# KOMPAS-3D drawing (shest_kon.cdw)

Referenced files: Чертеж Пример.cdw
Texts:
  Шестерня коническая
  Текст на чертеже
  Размерные надписи
  Шероховатость
  Линия-выноска #1
  Линия-выноска #2
  Линия-выноска #3
  Отклонения формы и база
  Заголовок таблицы
  Ячейка таблицы
  Стрелка вида
  Обозначение изменения
  Фигурная скобка
  Номер узла
  Марка координационной оси
  VRCB
  Выносная надпись
  Обозначение узла
  Марка/позиционное обозначение с линией-выноской
  Марка/позиционное обозначение на линии
  Марка/позиционное обозначение без линии-выноски
  2.*Размеры для справок.
  3.Неуказанные предельные отклонения размеров по H14; h14;  IT14/2.
  Внешний окружной модуль
  Число зубьев
  Тип зуба
  прямой
  Исходный контур
  ГОСТ13754-81
  Коэффициент смещения
  Коэффициент изменения
  толщины зуба
  Угол делительного конуса
  Степень точности
  Внешняя постоянная хорда зуба
  S ce
  Высота до внешней постоянной
  хорды зуба
  h ce
  Межосевой угол передачи
  Допуск на биение зубчатого венца
  Гарантированный боковой
  зазор в передаче
  Обозначение сопряженнго
  зубчатого колеса
  Ra 3,2
  Ra 1,25
  Ra 6,3
  Js9( 0,015)
  Js9
  Ra6,3
  Ra 12,5
  Шестерня
  коническая
Dimensions and other numbers on the sheet: 7; 1. 40...45 HRC.; 3; 20; 0; 45 00'00"; 8-В; 4,161 -0,093 -0,21; 2,243; 90 00'00"; 0,045; 0,08; 42,426*; 12; 38*; 27,88*; 5; 8; 15,08; 22,85; 43; 4; 1; 40; 40 09'; 0,04; 49 51'; 64,24; 22,8; 6; 0,06; 1:1; 0,25; 2; 9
